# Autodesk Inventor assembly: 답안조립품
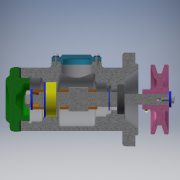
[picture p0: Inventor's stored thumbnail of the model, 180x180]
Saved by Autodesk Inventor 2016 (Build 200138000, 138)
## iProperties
Created: 2022-05
Part Number: 답안조립품
Material: 일반
Document SubType Name: Assembly
Designer: PC-1-3
Author: PC-1-3
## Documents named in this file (22)
- C:\Users\PC-1-3\Desktop\720506V1009\답안조립품.iam
- C:\Users\PC-1-3\Desktop\720506V1009\본체.ipt
- C:\Users\PC-1-3\Desktop\720506V1009\개스킷.ipt
- C:\Users\PC-1-3\Desktop\720506V1009\사이드 커버.ipt
- 사이드 커버.ipt
- C:\Users\PC-1-3\Desktop\720506V1009\축.ipt
- C:\Users\PC-1-3\Desktop\720506V1009\멈춤링 15 x 1.ipt
- C:\Users\PC-1-3\Desktop\720506V1009\멈춤링 35 x 1.6.ipt
- C:\Users\PC-1-3\Desktop\720506V1009\베어링 6202.ipt
- C:\Users\PC-1-3\Desktop\720506V1009\부시1.ipt
- C:\Users\PC-1-3\Desktop\720506V1009\부시2.ipt
- C:\Users\PC-1-3\Desktop\720506V1009\와셔 10 x 21.ipt
- C:\Users\PC-1-3\Desktop\720506V1009\너트 M10.ipt
- C:\Users\PC-1-3\Desktop\720506V1009\오일 실 15 x 30 x 7.ipt
- C:\Users\PC-1-3\Desktop\720506V1009\키 4 x 4.ipt
- C:\Users\PC-1-3\Desktop\720506V1009\V-벨트풀리.ipt
- C:\Users\PC-1-3\Desktop\720506V1009\멈춤나사 M3.ipt
- C:\Users\PC-1-3\Desktop\720506V1009\와셔 4 x 16.ipt
- C:\Users\PC-1-3\Desktop\720506V1009\볼트 M4 x 10.ipt
- C:\Users\PC-1-3\Desktop\720506V1009\탑 커버.ipt
- C:\Users\PC-1-3\Desktop\720506V1009\와셔 3 x 6.ipt
- C:\Users\PC-1-3\Desktop\720506V1009\십자볼트 M3 x 10.ipt
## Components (3 placed, 3 different names)
1. 개스킷:1
2. V-벨트풀리:1
3. ISO 4017 M4 x 10:1
